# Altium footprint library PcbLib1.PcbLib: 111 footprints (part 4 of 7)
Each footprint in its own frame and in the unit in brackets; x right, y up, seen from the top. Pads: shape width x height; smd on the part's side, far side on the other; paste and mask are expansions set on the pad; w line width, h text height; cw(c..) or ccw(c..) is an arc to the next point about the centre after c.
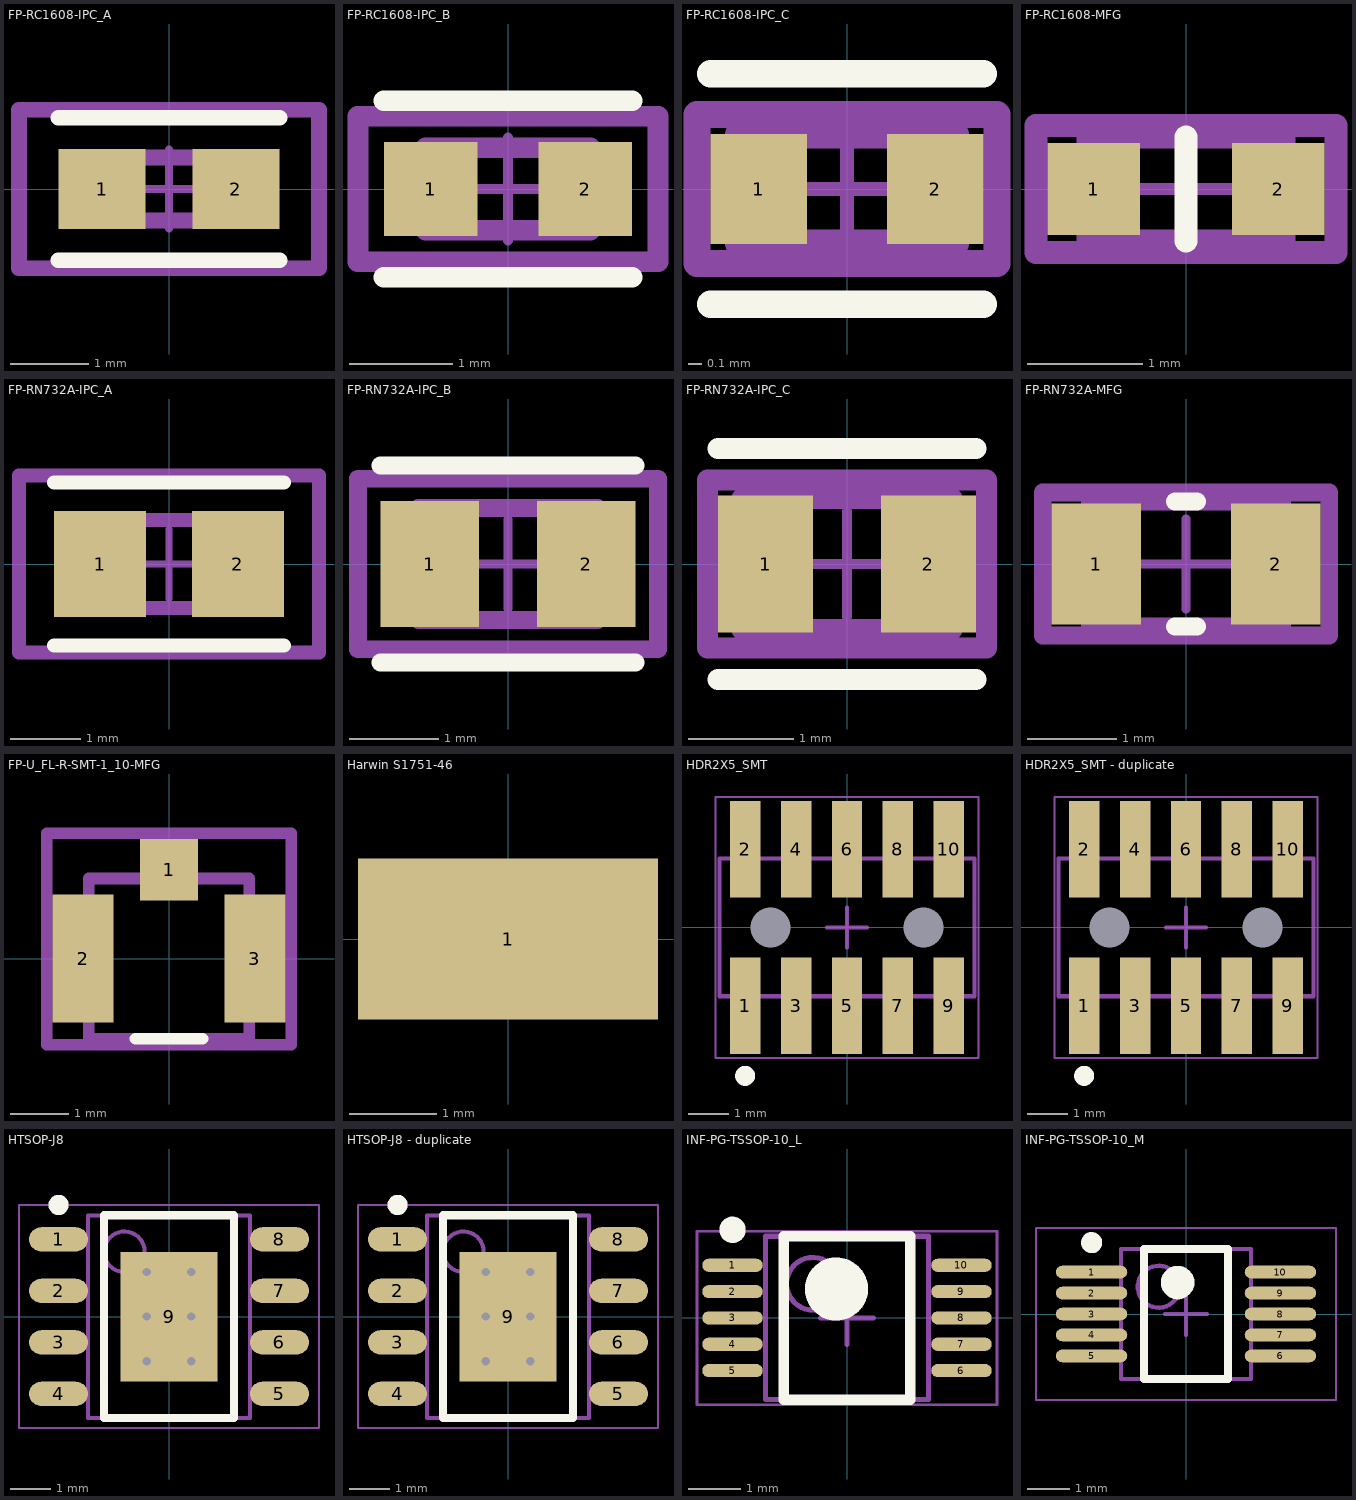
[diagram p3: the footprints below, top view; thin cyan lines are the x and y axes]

## FP-RC1608-IPC_A [mm]
pads (2):
  rect 1.11x1.012 smd paste+0 mask+0: 1(-0.851,0) 2(0.851,0)
Top Overlay:
  lines w0.2: -1.406,-0.906 1.406,-0.906 ; -1.406,0.906 1.406,0.906
Mechanical 5:
  lines w0.2: -1.906,-1.006 -1.906,1.006 1.906,1.006 1.906,-1.006 -1.906,-1.006
  text ".Designator" at 0,0.188 h1
Mechanical 13:
  lines w0.2: -0.8,-0.4 -0.8,0.4 0.8,0.4 0.8,-0.4 -0.8,-0.4
Mechanical 15:
  lines w0.2: -1.906,-1.006 -1.906,1.006 1.906,1.006 1.906,-1.006 -1.906,-1.006
Mechanical 16:
  lines w0.1: -0.5,0 0.5,0 ; 0,-0.5 0,0.5
3D body "Res_Samsung_RC1608F7873CS_eec.STEP": height 0.25, standoff 0, extent -1.906,-1.006 1.906,1.006

## FP-RC1608-IPC_B [mm]
pads (2):
  rect 0.91x0.912 smd paste+0 mask+0: 1(-0.751,0) 2(0.751,0)
Top Overlay:
  lines w0.2: -1.206,-0.856 1.206,-0.856 ; -1.206,0.856 1.206,0.856
Mechanical 5:
  lines w0.2: -1.456,-0.706 1.456,-0.706 1.456,0.706 -1.456,0.706 -1.456,-0.706
  text ".Designator" at 0,0.188 h1
Mechanical 13:
  lines w0.2: -0.8,-0.4 0.8,-0.4 0.8,0.4 -0.8,0.4 -0.8,-0.4
Mechanical 15:
  lines w0.2: -1.456,-0.706 1.456,-0.706 1.456,0.706 -1.456,0.706 -1.456,-0.706
Mechanical 16:
  lines w0.1: -0.5,0 0.5,0 ; 0,-0.5 0,0.5
3D body "Res_Samsung_RC1608F7873CS_eec.STEP": height 0.25, standoff 0, extent -1.456,-0.706 1.456,0.706

## FP-RC1608-IPC_C [mm]
pads (2):
  rect 0.71x0.812 smd paste+0 mask+0: 1(-0.651,0) 2(0.651,0)
Top Overlay:
  lines w0.2: -1.006,-0.85 1.006,-0.85 ; -1.006,0.85 1.006,0.85
Mechanical 5:
  lines w0.2: -1.106,-0.55 1.106,-0.55 1.106,0.55 -1.106,0.55 -1.106,-0.55
  text ".Designator" at 0,0.188 h1
Mechanical 13:
  lines w0.2: -0.8,-0.4 0.8,-0.4 0.8,0.4 -0.8,0.4 -0.8,-0.4
Mechanical 15:
  lines w0.2: -1.106,-0.55 1.106,-0.55 1.106,0.55 -1.106,0.55 -1.106,-0.55
Mechanical 16:
  lines w0.1: -0.5,0 0.5,0 ; 0,-0.5 0,0.5
3D body "Res_Samsung_RC1608F7873CS_eec.STEP": height 0.25, standoff 0, extent -1.106,-0.55 1.106,0.55

## FP-RC1608-MFG [mm]
pads (2):
  rect 0.8x0.8 smd paste+0 mask+0: 1(-0.8,0) 2(0.8,0)
Top Overlay:
  lines w0.2: 0,-0.45 0,0.45
Mechanical 5:
  lines w0.2: -1.3,-0.55 -1.3,0.55 1.3,0.55 1.3,-0.55 -1.3,-0.55
  text ".Designator" at 0,-0.001 h1
Mechanical 13:
  lines w0.2: -0.85,-0.45 -0.85,0.45 0.85,0.45 0.85,-0.45 -0.85,-0.45
Mechanical 15:
  lines w0.2: -1.3,-0.55 -1.3,0.55 1.3,0.55 1.3,-0.55 -1.3,-0.55
Mechanical 16:
  lines w0.1: -0.5,0 0.5,0 ; 0,-0.5 0,0.5
3D body "Res_Samsung_RC1608F7873CS_eec.STEP": height 0.25, standoff 0, extent -1.3,-0.55 1.3,0.55

## FP-RN732A-IPC_A [mm]
pads (2):
  rect 1.306x1.508 smd paste+0 mask+0: 1(-0.976,0) 2(0.976,0)
Top Overlay:
  lines w0.2: -1.629,-1.154 1.629,-1.154 ; -1.629,1.154 1.629,1.154
Mechanical 5:
  lines w0.2: -2.129,-1.254 2.129,-1.254 2.129,1.254 -2.129,1.254 -2.129,-1.254
  text ".Designator" at 0,0.188 h1
Mechanical 13:
  lines w0.2: -1,-0.625 1,-0.625 1,0.625 -1,0.625 -1,-0.625
Mechanical 15:
  lines w0.2: -2.129,-1.254 2.129,-1.254 2.129,1.254 -2.129,1.254 -2.129,-1.254
Mechanical 16:
  lines w0.1: -0.5,0 0.5,0 ; 0,-0.5 0,0.5
3D body "Res_TE_Connectivity_RN73C2A2K49B_eec.STEP": height 0.25, standoff 0, extent -2.129,-1.254 2.129,1.254

## FP-RN732A-IPC_B [mm]
pads (2):
  rect 1.106x1.408 smd paste+0 mask+0: 1(-0.876,0) 2(0.876,0)
Top Overlay:
  lines w0.2: -1.429,-1.104 1.429,-1.104 ; -1.429,1.104 1.429,1.104
Mechanical 5:
  lines w0.2: -1.679,-0.954 -1.679,0.954 1.679,0.954 1.679,-0.954 -1.679,-0.954
  text ".Designator" at 0,0.188 h1
Mechanical 13:
  lines w0.2: -1,-0.625 -1,0.625 1,0.625 1,-0.625 -1,-0.625
Mechanical 15:
  lines w0.2: -1.679,-0.954 -1.679,0.954 1.679,0.954 1.679,-0.954 -1.679,-0.954
Mechanical 16:
  lines w0.1: -0.5,0 0.5,0 ; 0,-0.5 0,0.5
3D body "Res_TE_Connectivity_RN73C2A2K49B_eec.STEP": height 0.25, standoff 0, extent -1.679,-0.954 1.679,0.954

## FP-RN732A-IPC_C [mm]
pads (2):
  rect 0.906x1.308 smd paste+0 mask+0: 1(-0.776,0) 2(0.776,0)
Top Overlay:
  lines w0.2: -1.229,-1.1 1.229,-1.1 ; -1.229,1.1 1.229,1.1
Mechanical 5:
  lines w0.2: -1.329,-0.8 1.329,-0.8 1.329,0.8 -1.329,0.8 -1.329,-0.8
  text ".Designator" at 0,0.188 h1
Mechanical 13:
  lines w0.2: -1,-0.625 1,-0.625 1,0.625 -1,0.625 -1,-0.625
Mechanical 15:
  lines w0.2: -1.329,-0.8 1.329,-0.8 1.329,0.8 -1.329,0.8 -1.329,-0.8
Mechanical 16:
  lines w0.1: -0.5,0 0.5,0 ; 0,-0.5 0,0.5
3D body "Res_TE_Connectivity_RN73C2A2K49B_eec.STEP": height 0.25, standoff 0, extent -1.329,-0.8 1.329,0.8

## FP-RN732A-MFG [mm]
pads (2):
  rect 1x1.35 smd paste+0 mask+0: 1(-1,0) 2(1,0)
Top Overlay:
  lines w0.2: -0.125,-0.7 0.125,-0.7 ; -0.125,0.7 0.125,0.7
Mechanical 5:
  lines w0.2: -1.6,-0.8 -1.6,0.8 1.6,0.8 1.6,-0.8 -1.6,-0.8
  text ".Designator" at 0,0.188 h1
Mechanical 13:
  lines w0.2: -1.075,-0.7 -1.075,0.7 1.075,0.7 1.075,-0.7 -1.075,-0.7
Mechanical 15:
  lines w0.2: -1.6,-0.8 -1.6,0.8 1.6,0.8 1.6,-0.8 -1.6,-0.8
Mechanical 16:
  lines w0.1: -0.5,0 0.5,0 ; 0,-0.5 0,0.5
3D body "Res_TE_Connectivity_RN73C2A2K49B_eec.STEP": height 0.25, standoff 0, extent -1.6,-0.8 1.6,0.8

## FP-U_FL-R-SMT-1_10-MFG [mm]
pads (3):
  rect 1x1.05 smd paste-1000 mask+0: 1(0,1.525)
  rect 1.05x2.2 smd paste-1000 mask+0: 2(-1.475,0) 3(1.475,0)
Top Overlay:
  lines w0.2: -0.575,-1.375 0.575,-1.375
Top Paste:
  rectangle: -1.95,-1 -1.05,1
  rectangle: 1.05,-1 1.95,1
  rectangle: -0.4,1.1 0.4,1.95
Mechanical 5:
  lines w0.2: -2.1,-1.475 2.1,-1.475 2.1,2.15 -2.1,2.15 -2.1,-1.475
  text ".Designator" at 0,0.337 h1
Mechanical 13:
  lines w0.2: -1.375,-1.375 1.375,-1.375 1.375,1.375 -1.375,1.375 -1.375,-1.375
Mechanical 15:
  lines w0.2: -2.1,-1.475 2.1,-1.475 2.1,2.15 -2.1,2.15 -2.1,-1.475
3D body "Conn_HIROSE_U_FL-R-SMT-1_10_eec.STEP": height 0.25, standoff 0, extent -2.1,-1.475 2.1,2.15

## Harwin S1751-46 [mm] "Test point smd 3.25x1.65x2mm"
height 2
pads (1):
  rect 3.45x1.85 smd: 1(0,0)
3D body "s1751-46.stp": height 2.01, standoff -0.04, extent -1.638,-0.827 1.612,0.823

## HDR2X5_SMT [mm] "Header, 10-Leads, Body 3.43x6.35mm, Pitch 1.27mm"
height 4.55
pads (12):
  rect 0.76x2.4 smd: 1(-2.54,-1.95) 2(-2.54,1.95) 3(-1.27,-1.95) 4(-1.27,1.95) 5(0,-1.95) 6(0,1.95) 7(1.27,-1.95) 8(1.27,1.95) 9(2.54,-1.95) 10(2.54,1.95)
  round 0 hole 1 unplated: MH1(-1.905,0) MH2(1.905,0)
Top Overlay:
  circle w0.25: c-2.54,-3.7 r0.125
Mechanical 13:
  lines w0.1: -3.175,-1.715 3.175,-1.715 3.175,1.715 -3.175,1.715 -3.175,-1.715
Mechanical 15:
  lines w0.05: -3.275,-3.25 -3.275,3.25 3.275,3.25 3.275,-3.25 -3.275,-3.25
  lines w0.1: -0.5,0 0.5,0 ; 0,-0.5 0,0.5
3D body: height 4.55, standoff 0.41, extent -3.175,-1.715 3.175,1.715

## HDR2X5_SMT - duplicate [mm] "Header, 10-Leads, Body 3.43x6.35mm, Pitch 1.27mm"
height 4.55
pads (12):
  rect 0.76x2.4 smd: 1(-2.54,-1.95) 2(-2.54,1.95) 3(-1.27,-1.95) 4(-1.27,1.95) 5(0,-1.95) 6(0,1.95) 7(1.27,-1.95) 8(1.27,1.95) 9(2.54,-1.95) 10(2.54,1.95)
  round 0 hole 1 unplated: MH1(-1.905,0) MH2(1.905,0)
Top Overlay:
  circle w0.25: c-2.54,-3.7 r0.125
Mechanical 13:
  lines w0.1: -3.175,-1.715 -3.175,1.715 3.175,1.715 3.175,-1.715 -3.175,-1.715
Mechanical 15:
  lines w0.05: -3.275,-3.25 3.275,-3.25 3.275,3.25 -3.275,3.25 -3.275,-3.25
  lines w0.1: -0.5,0 0.5,0 ; 0,-0.5 0,0.5
3D body: height 4.55, standoff 0.41, extent -3.175,-1.715 3.175,1.715

## HTSOP-J8 [mm] "HTSOP, 8-Leads, Body 4.90x3.90mm, Pitch 1.27mm, Thermal Pad 3.20x2.40mm, IPC Medium Density"
height 1
pads (9):
  oval 1.45x0.6 smd: 1(-2.725,1.905) 2(-2.725,0.635) 3(-2.725,-0.635) 4(-2.725,-1.905) 5(2.725,-1.905) 6(2.725,-0.635) 7(2.725,0.635) 8(2.725,1.905)
  rect 2.4x3.2 smd: 9(0,0)
via -0.55,1.1 diameter 0.5 hole 0.2
via 0.55,1.1 diameter 0.5 hole 0.2
via -0.55,0 diameter 0.5 hole 0.2
via 0.55,0 diameter 0.5 hole 0.2
via -0.55,-1.1 diameter 0.5 hole 0.2
via 0.55,-1.1 diameter 0.5 hole 0.2
Top Overlay:
  circle w0.25: c-2.725,2.755 r0.125
  lines w0.2: -1.6,-2.5 -1.6,2.5 1.6,2.5 1.6,-2.5 -1.6,-2.5
Mechanical 13:
  circle w0.1: c-1.1,1.6 r0.5
  lines w0.1: -2,-2.5 -2,2.5 2,2.5 2,-2.5 -2,-2.5
Mechanical 15:
  lines w0.05: -3.7,-2.75 -3.7,2.75 3.7,2.75 3.7,-2.75 -3.7,-2.75
  lines w0.1: -0.5,0 0.5,0 ; 0,-0.5 0,0.5
3D body: height 1, standoff 0, extent -2,-2.5 2,2.5

## HTSOP-J8 - duplicate [mm] "HTSOP, 8-Leads, Body 4.90x3.90mm, Pitch 1.27mm, Thermal Pad 3.20x2.40mm, IPC Medium Density"
height 1
pads (9):
  oval 1.45x0.6 smd: 1(-2.725,1.905) 2(-2.725,0.635) 3(-2.725,-0.635) 4(-2.725,-1.905) 5(2.725,-1.905) 6(2.725,-0.635) 7(2.725,0.635) 8(2.725,1.905)
  rect 2.4x3.2 smd: 9(0,0)
via -0.55,1.1 diameter 0.5 hole 0.2
via 0.55,1.1 diameter 0.5 hole 0.2
via -0.55,0 diameter 0.5 hole 0.2
via 0.55,0 diameter 0.5 hole 0.2
via -0.55,-1.1 diameter 0.5 hole 0.2
via 0.55,-1.1 diameter 0.5 hole 0.2
Top Overlay:
  circle w0.25: c-2.725,2.755 r0.125
  lines w0.2: -1.6,-2.5 -1.6,2.5 1.6,2.5 1.6,-2.5 -1.6,-2.5
Mechanical 13:
  circle w0.1: c-1.1,1.6 r0.5
  lines w0.1: -2,-2.5 -2,2.5 2,2.5 2,-2.5 -2,-2.5
Mechanical 15:
  lines w0.05: -3.7,-2.75 -3.7,2.75 3.7,2.75 3.7,-2.75 -3.7,-2.75
  lines w0.1: -0.5,0 0.5,0 ; 0,-0.5 0,0.5
3D body: height 1, standoff 0, extent -2,-2.5 2,2.5

## INF-PG-TSSOP-10_L [mm] "SOP, 10-Leads, Body 3x3 mm, Pitch 0.5 mm, IPC High Density"
height 1.05
pads (10):
  oval 1.15x0.25 smd: 1(-2.175,1) 2(-2.175,0.5) 3(-2.175,0) 4(-2.175,-0.5) 5(-2.175,-1) 6(2.175,-1) 7(2.175,-0.5) 8(2.175,0) 9(2.175,0.5) 10(2.175,1)
Top Overlay:
  circle w0.25: c-2.175,1.675 r0.125
  circle w0.6: c-0.2,0.55 r0.3
  lines w0.2: -1.2,-1.55 -1.2,1.55 1.2,1.55 1.2,-1.55 -1.2,-1.55
Mechanical 13:
  circle w0.1: c-0.65,0.65 r0.5
  lines w0.1: -1.55,-1.55 -1.55,1.55 1.55,1.55 1.55,-1.55 -1.55,-1.55
Mechanical 15:
  lines w0.05: -2.85,-1.65 -2.85,1.65 2.85,1.65 2.85,-1.65 -2.85,-1.65
  lines w0.1: -0.5,0 0.5,0 ; 0,-0.5 0,0.5
3D body: height 1.05, standoff 0.1, extent -1.55,-1.55 1.55,1.55

## INF-PG-TSSOP-10_M [mm] "SOP, 10-Leads, Body 3x3 mm, Pitch 0.5 mm, IPC Low Density"
height 1.05
pads (10):
  oval 1.7x0.3 smd: 1(-2.25,1) 2(-2.25,0.5) 3(-2.25,0) 4(-2.25,-0.5) 5(-2.25,-1) 6(2.25,-1) 7(2.25,-0.5) 8(2.25,0) 9(2.25,0.5) 10(2.25,1)
Top Overlay:
  circle w0.4: c-0.2,0.75 r0.2
  circle w0.25: c-2.25,1.7 r0.125
  lines w0.2: -1,-1.55 1,-1.55 1,1.55 -1,1.55 -1,-1.55
Mechanical 13:
  circle w0.1: c-0.65,0.65 r0.5
  lines w0.1: -1.55,-1.55 1.55,-1.55 1.55,1.55 -1.55,1.55 -1.55,-1.55
Mechanical 15:
  lines w0.05: -3.575,-2.05 3.575,-2.05 3.575,2.05 -3.575,2.05 -3.575,-2.05
  lines w0.1: -0.5,0 0.5,0 ; 0,-0.5 0,0.5
3D body: height 1.05, standoff 0.1, extent -1.55,-1.55 1.55,1.55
